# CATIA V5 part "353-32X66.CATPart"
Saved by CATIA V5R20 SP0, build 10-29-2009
Part number: 353-32X66
Definition: NONE
Nomenclature: 353-32X66
Source: Unknown
Description: 353-32X66
Bounding box of the stored display mesh (mm): x -7 to 59, y -22.5 to 22.5, z -22.5 to 22.5
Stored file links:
  C:\Users\Utente\Desktop\IO LAVORO\3D X SITO CF\X SITO\PLASTICA\353\353-32X66.CATPart
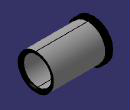
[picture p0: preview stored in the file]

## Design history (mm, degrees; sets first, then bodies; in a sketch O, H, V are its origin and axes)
Body1 "353-32X66" (main body)
  Solid1: solid without history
